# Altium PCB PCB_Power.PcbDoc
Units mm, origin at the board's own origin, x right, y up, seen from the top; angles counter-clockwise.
Board outline 67.04 x 64.5 mm, 2 copper layers (M1(Top_copper), M2(Bottom copper), stack 0.325 mm thick; 22 components, 12 nets, 59 pads, 2 vias.
Unrouted connection lines stored in the file: 1.
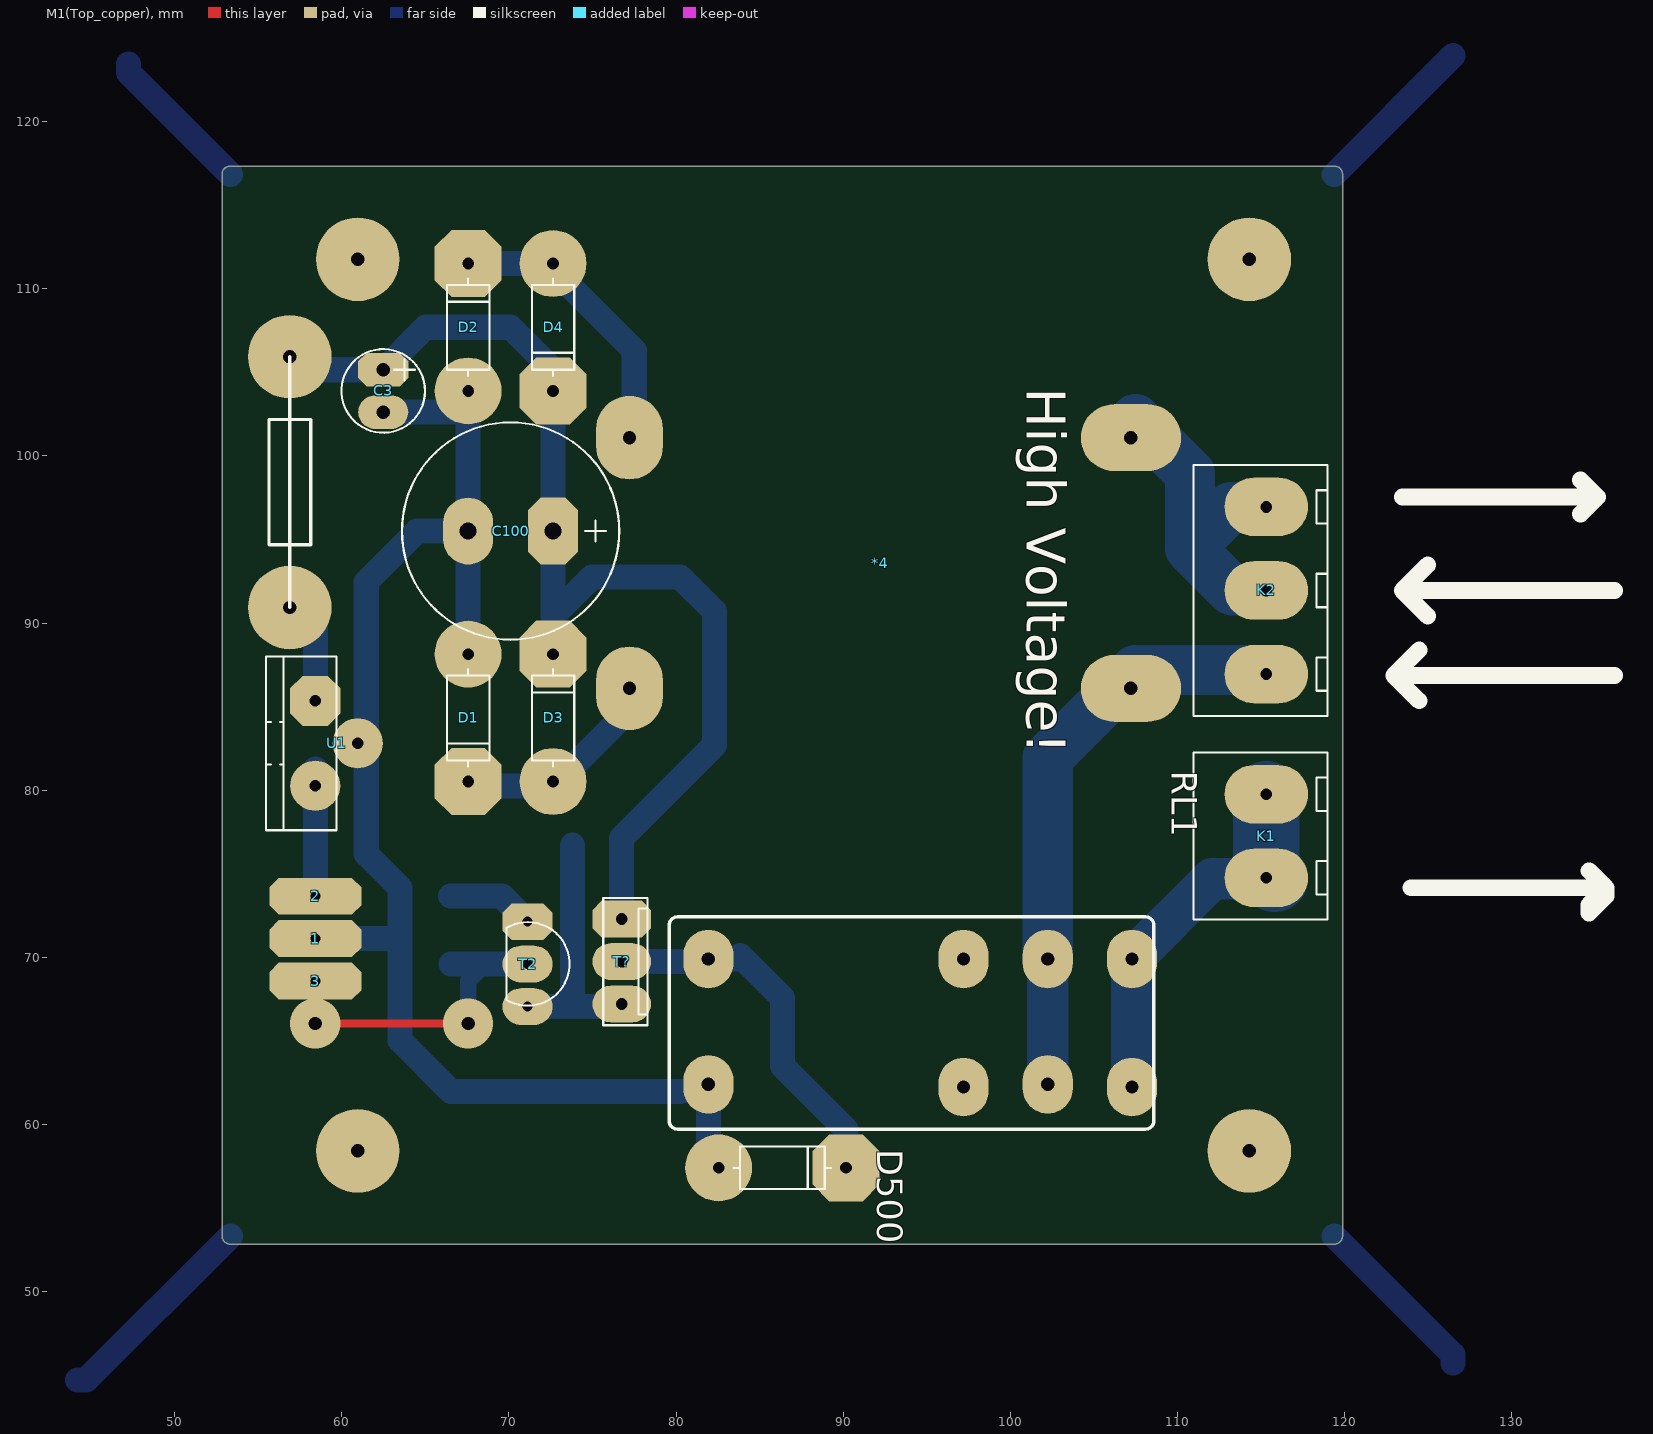
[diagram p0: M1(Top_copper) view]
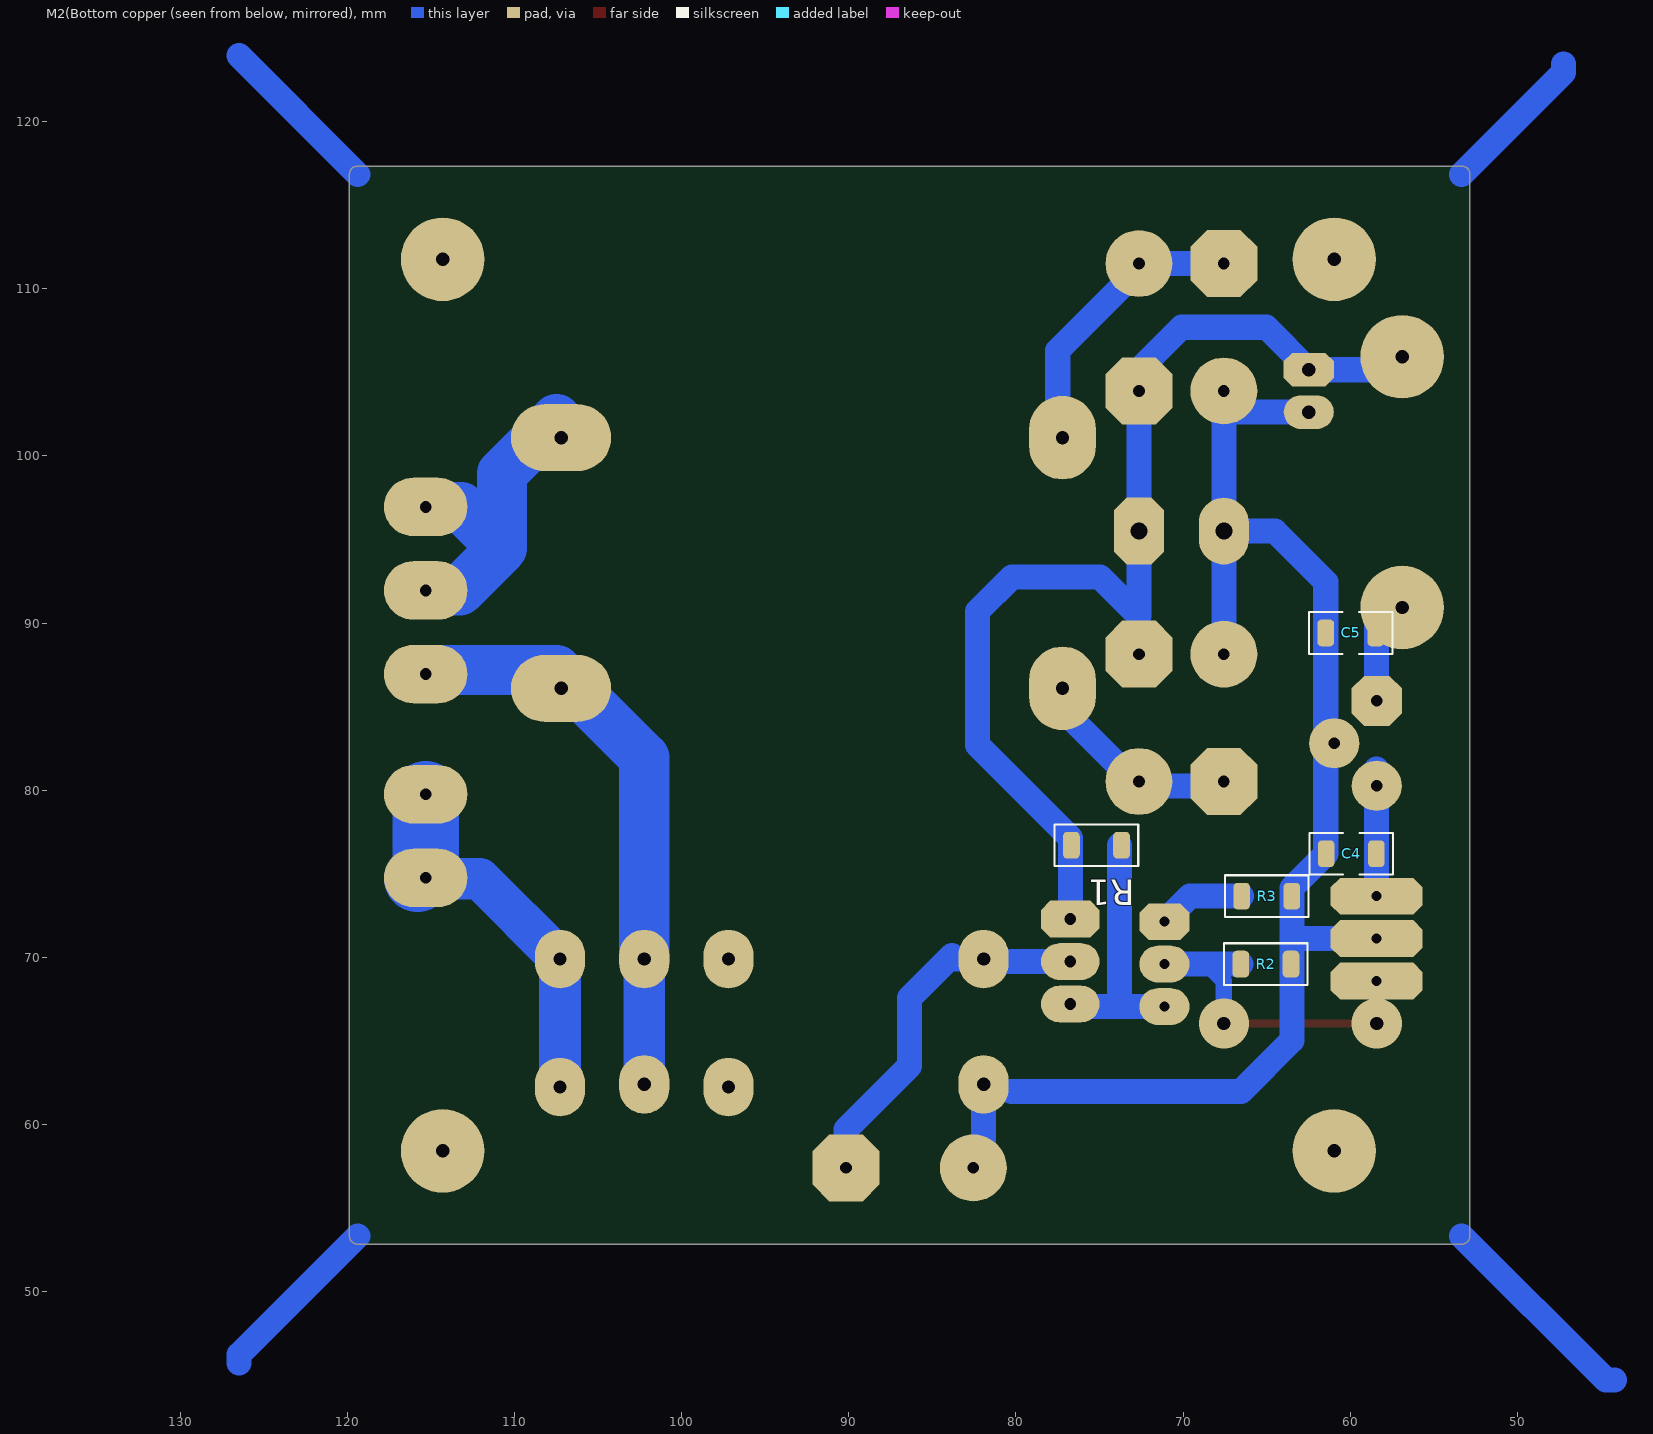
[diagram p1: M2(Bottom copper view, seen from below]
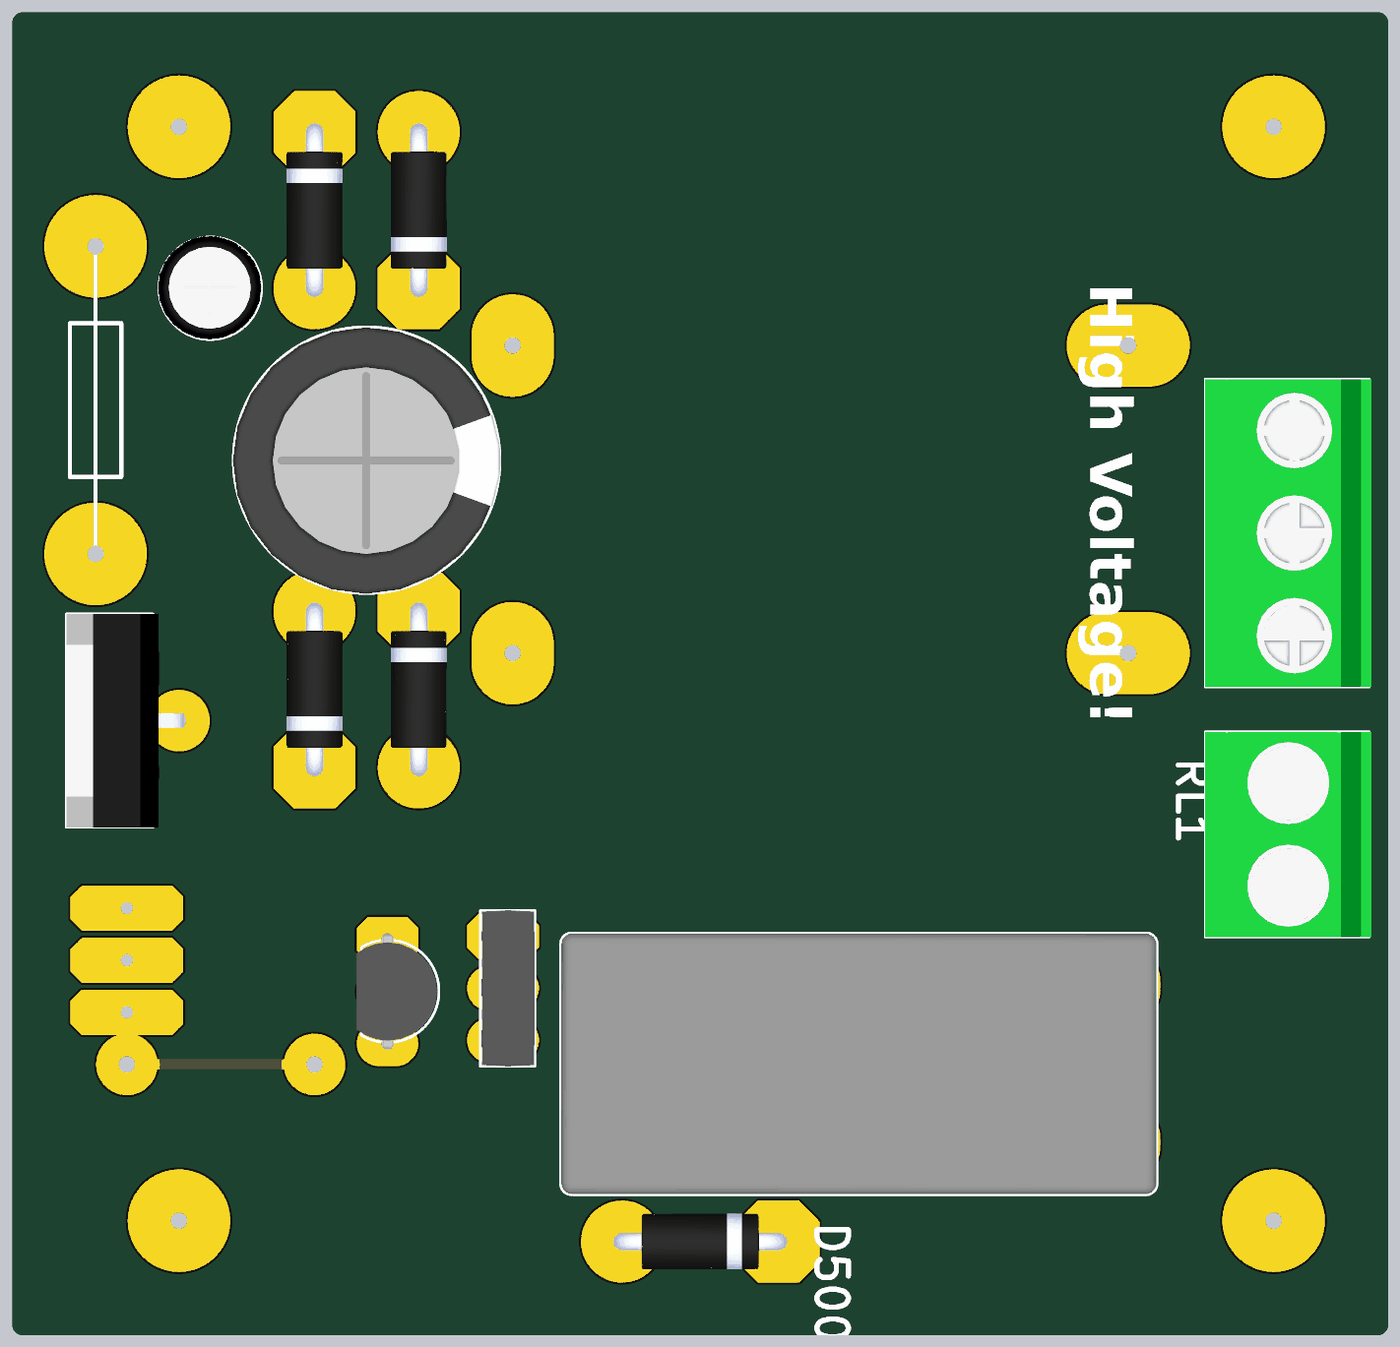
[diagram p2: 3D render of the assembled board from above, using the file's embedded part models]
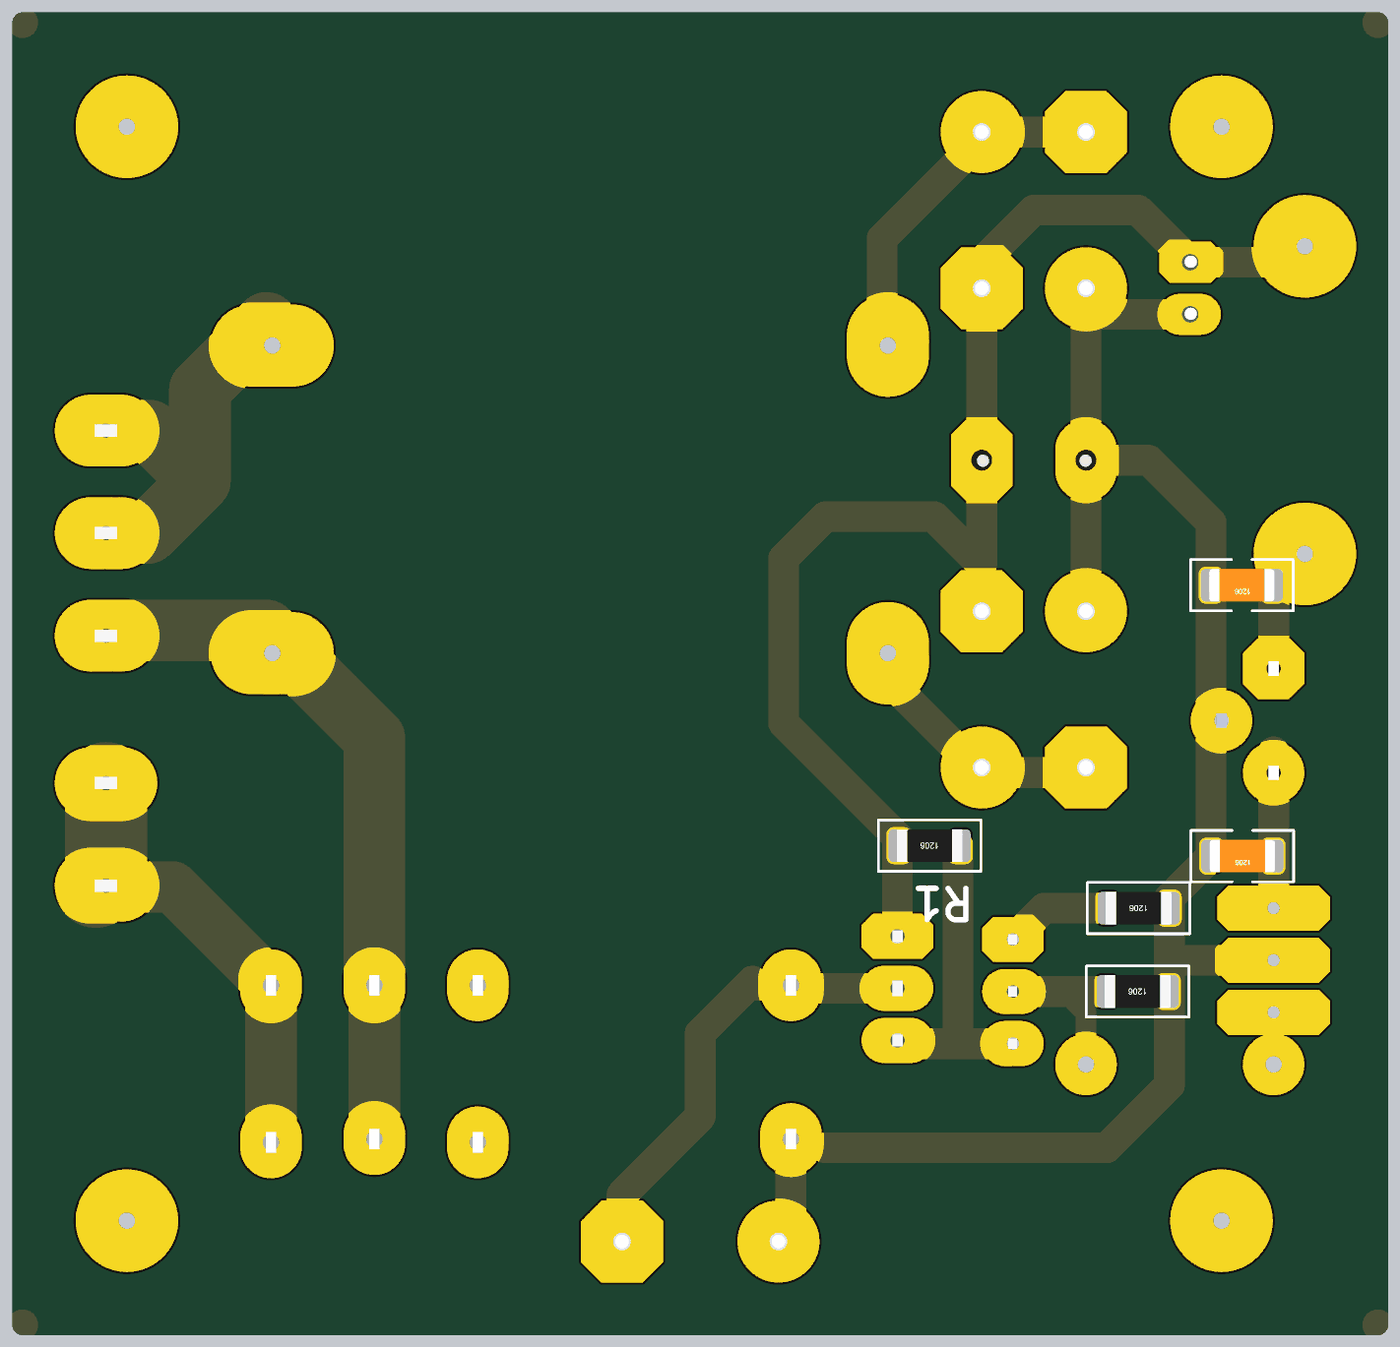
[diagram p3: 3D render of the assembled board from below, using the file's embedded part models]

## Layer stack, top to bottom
Top Solder: solder mask 0.0102, Solder Resist, Dk 3.5
M1(Top_copper): signal copper 0.0356
Dielectric 1: core 0.254, FR-4, Dk 4.2
M2(Bottom copper: signal copper 0.0356
Bottom Solder: solder mask 0.0102, Solder Resist, Dk 3.5

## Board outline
53.34,52.84 cw(c53.34,53.34) 52.84,53.34 52.84,116.84 cw(c53.34,116.84) 53.34,117.34 119.38,117.34 cw(c119.38,116.84) 119.88,116.84 119.88,53.34 cw(c119.38,53.34) 119.38,52.84

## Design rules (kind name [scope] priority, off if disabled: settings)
AssemblyTestPointUsage [All] p1 off:
AssemblyTestpoint [All] p1 off: testpointundercomponent=TRUE minsize=1.016 maxsize=2.54 preferedsize=1.524 minholesize=0 maxholesize=1.016 preferedholesize=0.813 testpointgrid=0.025 usegrid=TRUE gridtolerance=0 allowsidetop=TRUE allowsidebottom=TRUE
Clearance Clearance_GND [All vs InNet('No Net')] p1: gap=0.254 except(0.5: Arc-Poly Track-Poly SMDPad-Poly THPad-Poly Via-Poly Fill-Poly Poly-Poly; 0.7: Arc-Region Track-Region SMDPad-Region THPad-Region Via-Region Fill-Region Poly-Region Region-Region)
Clearance isairon_rule [All] p2: gap=0.254 // Для изучения
Clearance [All] p3: gap=0.254 except(0.5: Arc-Poly Track-Poly SMDPad-Poly THPad-Poly Via-Poly Fill-Poly Poly-Poly; 0.7: Arc-Region Track-Region SMDPad-Region THPad-Region Via-Region Fill-Region Poly-Region Region-Region)
ComponentClearance [All] p1: gap=0.5 collisioncheckmode=3 verticalgap=0.5 showdistances=FALSE
FabricationTestPointUsage [All] p1 off: valid=0 allowmultiple=FALSE
FabricationTestpoint [All] p1 off: side=3 testpointundercomponent=TRUE minsize=1.016 maxsize=2.54 preferedsize=1.524 minholesize=0 maxholesize=1.016 preferedholesize=0.813 testpointgrid=0.025 allowsidetop=TRUE allowsidebottom=TRUE usegrid=TRUE gridtolerance=0
PasteMaskExpansion [All] p1 off: expansion=0
PolygonConnect [All] p1: connectstyle=Relief reliefconductorwidth=0.254 reliefentries=4 polygonreliefangle="90 Angle" airgapwidth=0.254
RoutingVias [All] p1: holewidth=0.8 width=1.5 viastyle="Through Hole" minholewidth=0.5 minwidth=1 maxholewidth=1.5 maxwidth=2.5
SolderMaskExpansion [All] p1 off: expansion=0.102
Width [All] p1: maxlimit=4 minlimit=0.5 preferedwidth=1 toplayer_maxwidth=2 minimp=50.000000 maximp=50.000000 favimp=50.000000
24 further rules are at their usual default settings.

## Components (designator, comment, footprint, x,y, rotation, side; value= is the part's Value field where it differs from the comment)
1 "FAT_single_BLC_pin" Single_BLC_fat_Pin 58.42,71.12 r90 top
2 "FAT_single_BLC_pin" Single_BLC_fat_Pin 58.42,73.66 r270 top
3 "FAT_single_BLC_pin" Single_BLC_fat_Pin 58.42,68.58 r270 top
*4 "Trans12V" Trans_12V 107.216,111.092 r180 top
C3 "10u" El-d5-h11-F2.54 62.484,103.886 r90 top
C4 "100n" C1206(3216) 59.944,76.2 r0 bottom
C5 "100n" C1206(3216) 59.968,89.408 r0 bottom
C100 "2200u" El-d13-h21-F5.08 70.104,95.504 r0 top
D1 "1N4746" DO-41-300 67.564,84.328 r270 top
D2 "1N4746" DO-41-300 67.564,107.696 r90 top
D3 "1N4746" DO-41-300 72.644,84.328 r90 top
D4 "1N4746" DO-41-300 72.644,107.696 r270 top
D500 "1N4746" DO-41-300 86.36,57.404 r0 top
K1 "TS-501 2P" "TS-501 2P-2.5" 115.316,77.256 r90 top
K2 "TS-501 3P" "TS-501 3P-2.5" 115.316,91.948 r90 top
R1 "1k" R1206 75.184,76.708 r0 bottom
R2 "1k" R1206 65.048,69.596 r0 bottom
R3 "1k" R1206 65,73.66 r0 bottom
RL1 "REL_TYCO_SCHRACK_RT31xxxx" REL_TYCO_SCHRACK_RT31XXXX 94.09,66.07 r0 top
T2 "2N4401" TO92C1 71.12,69.596 r270 top
T? "BD238" TO126-10 76.75,69.75 r270 top
U1 "7805" "TO220-1A 2.54" 58.42,82.804 r90 top

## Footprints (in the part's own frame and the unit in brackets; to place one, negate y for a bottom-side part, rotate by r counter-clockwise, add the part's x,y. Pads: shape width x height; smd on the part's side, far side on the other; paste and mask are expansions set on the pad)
C1206(3216) [mm]
  rrect50% 1x1.6 smd: 1(-1.5,0) 2(1.5,0)
  silkscreen extent -2.5,-1.25 2.5,1.25, body extent -1.6,-0.8 1.6,0.8, height 1
DO-41-300 [mm]
  round 4 hole 0.7: 1(-3.81,0)
  oct 4x4 hole 0.7: 2(3.81,0)
  silkscreen extent -2.92,-1.27 2.92,1.27, body extent -4.24,-1.36 4.24,1.36, height 2.81
El-d5-h11-F2.54 [mm]
  oct 2x3 hole 0.8: 1(1.27,0)
  oval 2x3 hole 0.8: 2(-1.27,0)
  silkscreen extent -2.5,-2.5 2.5,2.5, body extent -2.5,-2.5 2.55,2.55, height 11.53
El-d13-h21-F5.08 [mm]
  oct 3x4 hole 1.016: 1(2.54,0)
  oval 3x4 hole 1.016: 2(-2.54,0)
  silkscreen extent -6.5,-6.5 6.5,6.5, body extent -6.52,-6.51 6.52,6.47, height 21.55
R1206 [mm]
  rrect50% 1x1.6 smd: 1(-1.5,0) 2(1.5,0)
  silkscreen extent -2.5,-1.25 2.5,1.25, body extent -1.6,-0.8 1.6,0.8, height 0.6
REL_TYCO_SCHRACK_RT31XXXX [mm] "8 Leads, Row Spacing 7.62 mm; Body 29mm x 12.7mm, TYCO RT Serie"
  oval 3x3.5 hole 0.8: 11(8.15,-3.67) 11(8.15,3.83) 12(3.11,-3.83) 12(3.11,3.83) 14(13.19,-3.83) 14(13.19,3.83) A1(-12.15,-3.67) A2(-12.15,3.83)
  silkscreen extent -14.5,-6.35 14.5,6.35, body extent -14.5,-6.35 14.5,6.35, height 15.7
Single_BLC_fat_Pin [mm]
  oct 2.2x5.5 hole 0.6: 0(0,0)
TO92C1 [mm]
  oval 2.2x3 hole 0.6: 1(2.54,0) 2(0,0)
  oct 2.2x3 hole 0.6: 3(-2.54,0)
  silkscreen extent -2.51,-1.27 2.49,2.51, body extent -2.79,-1.52 2.79,2.41, height 8
TO126-10 [mm]
  oct 2.2x3.5 hole 0.7: 1(-2.54,0)
  oval 2.2x3.5 hole 0.7: 2(0,0) 3(2.54,0)
  silkscreen extent -3.81,-1.1 3.81,1.55, body extent -3.81,-1.04 3.81,1.55, height 13.02
"TO220-1A 2.54" [mm]
  round 3 hole 0.7: 1(-2.54,0) 2(0,-2.54)
  oct 3x3 hole 0.7: 3(2.54,0)
  silkscreen extent -5.2,-1.27 5.2,2.95, body extent -5.2,-2.79 5.2,2.95, height 23.29
Trans_12V [mm]
  oval 6x4 hole 0.8 unplated: 1(0,25) 2(0,10)
  oval 4x5 hole 0.8 unplated: 3(30,25) 4(30,10)
  body extent -0.35,0 30.35,35, height 35
"TS-501 2P-2.5" [mm]
  oval 3.5x5 hole 0.7: 1(-2.5,0) 2(2.5,0)
  silkscreen extent -5,-3.65 5,4.35, body extent -5,-3.75 5,4.35, height 1.5
"TS-501 3P-2.5" [mm]
  oval 3.5x5 hole 0.7: 1(-5,0) 2(0,0) 3(5,0)
  silkscreen extent -7.5,-3.65 7.5,4.35, body extent -7.5,-3.75 7.5,4.35, height 1.5

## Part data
C3: library part 10u-35V, "35V"
C4 C5: library part C_1206, "SMD-0805 50V Y5V +80/-20%"
C100: library part "2200u-16V 105F", "16V 105C 39m 1.9A"
D1 D2 D3 D4 D500: "18V 1W"
K1 K2: "10A/300V AC 5mm"
R1 R2 R3: library part R-1206-1%, "SMD 1206 0.125W 1% 200V"
RL1: library part REL_TYCO_SCHRACK_RT314012, "RT PCB Relay Form C (1 CO Contact)"
T2: "40V 0.6A 250MHz 6.5pF (5V)"
T?: "80V 2A 3MHz"

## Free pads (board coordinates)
  round 5 hole 0.8 unplated: 44(56.896,90.932) 45(56.896,105.932) 46(114.3,111.76) 47(114.3,58.42) 48(60.96,58.42) 49(60.96,111.76)

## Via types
v1: diameter 3, hole 0.8, M1(Top_copper) to M2(Bottom copper, 2 vias

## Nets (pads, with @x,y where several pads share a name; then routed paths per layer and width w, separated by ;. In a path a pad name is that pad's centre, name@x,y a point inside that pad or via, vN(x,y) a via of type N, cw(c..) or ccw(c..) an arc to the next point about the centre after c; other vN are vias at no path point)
12V: C3.1 C5.1 C100.1 D3.2 D4.2 R1.2 T?.1 U1.3 | length 70.1
  M2(Bottom copper w1.5: 56.896,105.932 57.672,105.156 C3.1 65.024,107.696 70.104,107.696 72.644,105.156 D4.2 C100.1 72.644,90.424 74.97,92.75 80.25,92.75 82.296,90.704 82.296,82.696 76.75,77.15 T?.1 ; 57.404,90.932 58.42,89.916 U1.3@58.42,86.36
GND: 1.0 C3.2 C4.2 C5.2 C100.2 D1.1 D2.1 D500.1 R2.1 R3.1 RL1.A1 U1.2 | length 83.6
  M2(Bottom copper w1.5: 1.0@57.912,71.12 62.992,71.12 ; C3.2 67.564,102.616 C100.2 ; D1.1 C100.2 ; 80.264,61.976 66.548,61.976 63.5,65.024 63.5,74.144 C4.2 61.468,76.224 C5.2 61.468,92.456 64.516,95.504 C100.2 ; RL1.A1 81.94,58.014 D500.1
Net2_0: 2.0 C4.1 U1.1 | length 7.1
  M2(Bottom copper w1.5: 2.0@58.42,74.168 U1.1@58.42,81.28
Net3_0: 3.0 R2.2 T2.2 | length 20.2
  M1(Top_copper) w0.5: v1(58.42,66.04) v1(67.564,66.04)
  M2(Bottom copper w1: v1(58.42,66.04) 3.0 ; v1(67.564,66.04) 67.564,68.58 68.58,69.596
  M2(Bottom copper w1.5: R2.2 68.58,69.596 T2.2
Net*4_1: *4.1 K2.1 RL1.11 | length 34.9
  M2(Bottom copper w2.5: RL1.11@102.24,62.4 RL1.11@102.24,69.9
  M2(Bottom copper w3: RL1.11@102.24,69.9 102.24,81.94 107.5,87.2 115.064,87.2 K2.1
Net*4_2: *4.2 K2.2 K2.3 | length 20.3
  M2(Bottom copper w3: *4.2@107.5,102.2 110.744,98.956 110.744,94.488 ; K2.2 113.284,91.948 110.744,94.488 ; K2.3 113.204,96.948 110.744,94.488
Net*4_3: *4.3 D1.2 D3.1 | length 14.1
  M2(Bottom copper w1.5: D1.2 67.818,80.264 72.664,80.264 77.5,85.1 *4.3@77.5,87.2
Net*4_4: *4.4 D2.2 D4.1 | length 16.2
  M2(Bottom copper w1.5: D2.2 72.296,111.506 77.5,106.302 *4.4@77.5,102.2
NetD500_2: D500.2 RL1.A2 T?.2 | length 22.5
  M2(Bottom copper w1.5: T?.2@76.85,69.65 T?.2 RL1.A2@81.79,69.75 ; RL1.A2 83.616,69.9 83.82,70.104 86.36,67.564 86.36,63.5 90.17,59.69 D500.2
NetK1_2: K1.2 RL1.14 | length 23.4
  M2(Bottom copper w2.5: RL1.14@107.28,62.24 107.28,69.9 112.08,74.7 115.8,74.7
  M2(Bottom copper w4: K1.2 115.316,75.184 115.8,74.7
NetR1_1: R1.1 T2.1 T?.3 | length 15.3
  M2(Bottom copper w1.5: T2.1 76.596,67.056 T?.3 ; 73.8,67.11 R1.1@73.8,76.708
NetR3_2: R3.2 T2.3 | length 5.3
  M2(Bottom copper w1.5: R3.2 69.596,73.66 T2.3
pads on no net: K1.1 RL1.12
copper on no net: | length 42.5
  M2(Bottom copper w1.5: 44.196,44.704 44.704,44.704 53.34,53.34 ; 47.244,123.444 47.244,122.936 53.34,116.84 ; 119.38,53.34 126.492,46.228 126.492,45.72 ; 119.38,116.84 126.492,123.952

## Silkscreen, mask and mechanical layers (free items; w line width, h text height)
Top Overlay:
  lines w0.2: 56.896,90.932 56.896,105.932 ; 55.646,94.682 58.146,94.682 58.146,102.182 55.646,102.182 55.646,94.682
  lines w1: 123.444,97.536 135.128,97.536 ; 123.952,74.168 135.636,74.168 ; 124.46,85.344 122.936,86.868 ; 124.46,88.392 122.936,86.868 ; 124.968,90.424 123.444,91.948 ; 124.968,93.472 123.444,91.948 ; 134.112,96.52 135.128,97.536 ; 134.112,98.552 135.128,97.536 ; 134.62,75.184 135.636,74.168 ; 136.144,86.868 122.936,86.868 ; 136.144,91.948 123.444,91.948 ; 135.636,74.168 135.636,73.66 134.62,72.644 134.62,73.152 135.636,74.168
0 (Board_boarders):
  lines w1: 53.34,53.34 119.38,53.34 ; 53.34,53.34 53.34,116.84 ; 53.34,53.34 53.34,116.84 ; 53.34,53.34 119.38,53.34 ; 53.34,116.84 119.38,116.84 ; 53.34,116.84 119.38,116.84 ; 119.38,53.34 119.38,116.84 ; 119.38,53.34 119.38,116.84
